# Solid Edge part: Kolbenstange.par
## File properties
Username: bmolnar
Dokumentum tartalom típus: 0
Author: bmolnar
Last saved by: bmolnar
Revision: 80
Sűrűség: 0,000 kg/m^3
Pontosság: 0,990
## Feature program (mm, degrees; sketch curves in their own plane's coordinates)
base feature "unnamed BaseFeature 1"
thread "unnamed Thread 1"
sketch for "unnamed Protrusion 1" plane through (0, 0, -18.5) normal (0, 0, -1) x-axis (0, -1, 0)
  circle centre (0, 0) radius 12.5
extrude "unnamed Protrusion 1" add finite 14 along +normal
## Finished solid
Body 1: solid body, 17 faces, 23 edges, 8 vertices.
  Faces by surface: plane 8, cylinder 4, torus 3, cone 2
  Edges by curve: circle 13, line 6, ellipse 2, intersection 2
Bounding box of the edges (mm; curved faces can reach further): 25.000 x 25.000 x 73.500, from (-12.5, -12.5, -32.5) to (12.5, 12.5, 41).
Cylindrical faces by radius (mm): R2.9 x1, R4 x1, R5 x1, R12.5 x1
Conical faces (half-angle, radius in mm at the cone's reference point): 20 deg R3.5 x1, 60 deg R3.55 x1
Toroidal faces (ring radius, tube radius in mm): R3.3 r0.4 x2, R3.8 r1.2 x1
Planar faces by outward normal: +x 1, +z 3, -x 1, -z 1, oblique 2
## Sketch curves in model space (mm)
circle centre (0, 0, -18.5) radius 12.5
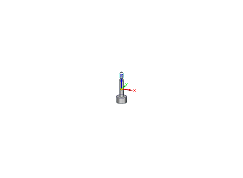
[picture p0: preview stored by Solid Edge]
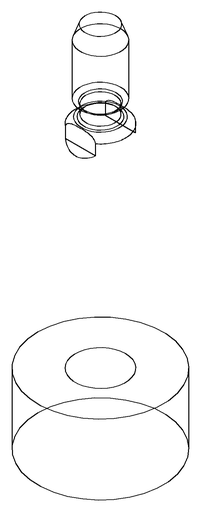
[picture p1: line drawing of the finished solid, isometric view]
